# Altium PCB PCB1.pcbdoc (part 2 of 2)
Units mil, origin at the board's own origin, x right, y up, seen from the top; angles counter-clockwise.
Board outline 3879.65 x 2893.58 mil, 4 copper layers (Top Layer, Inner1, Inner2, Bottom Layer); 142 components, 140 nets, 675 pads, 157 vias.
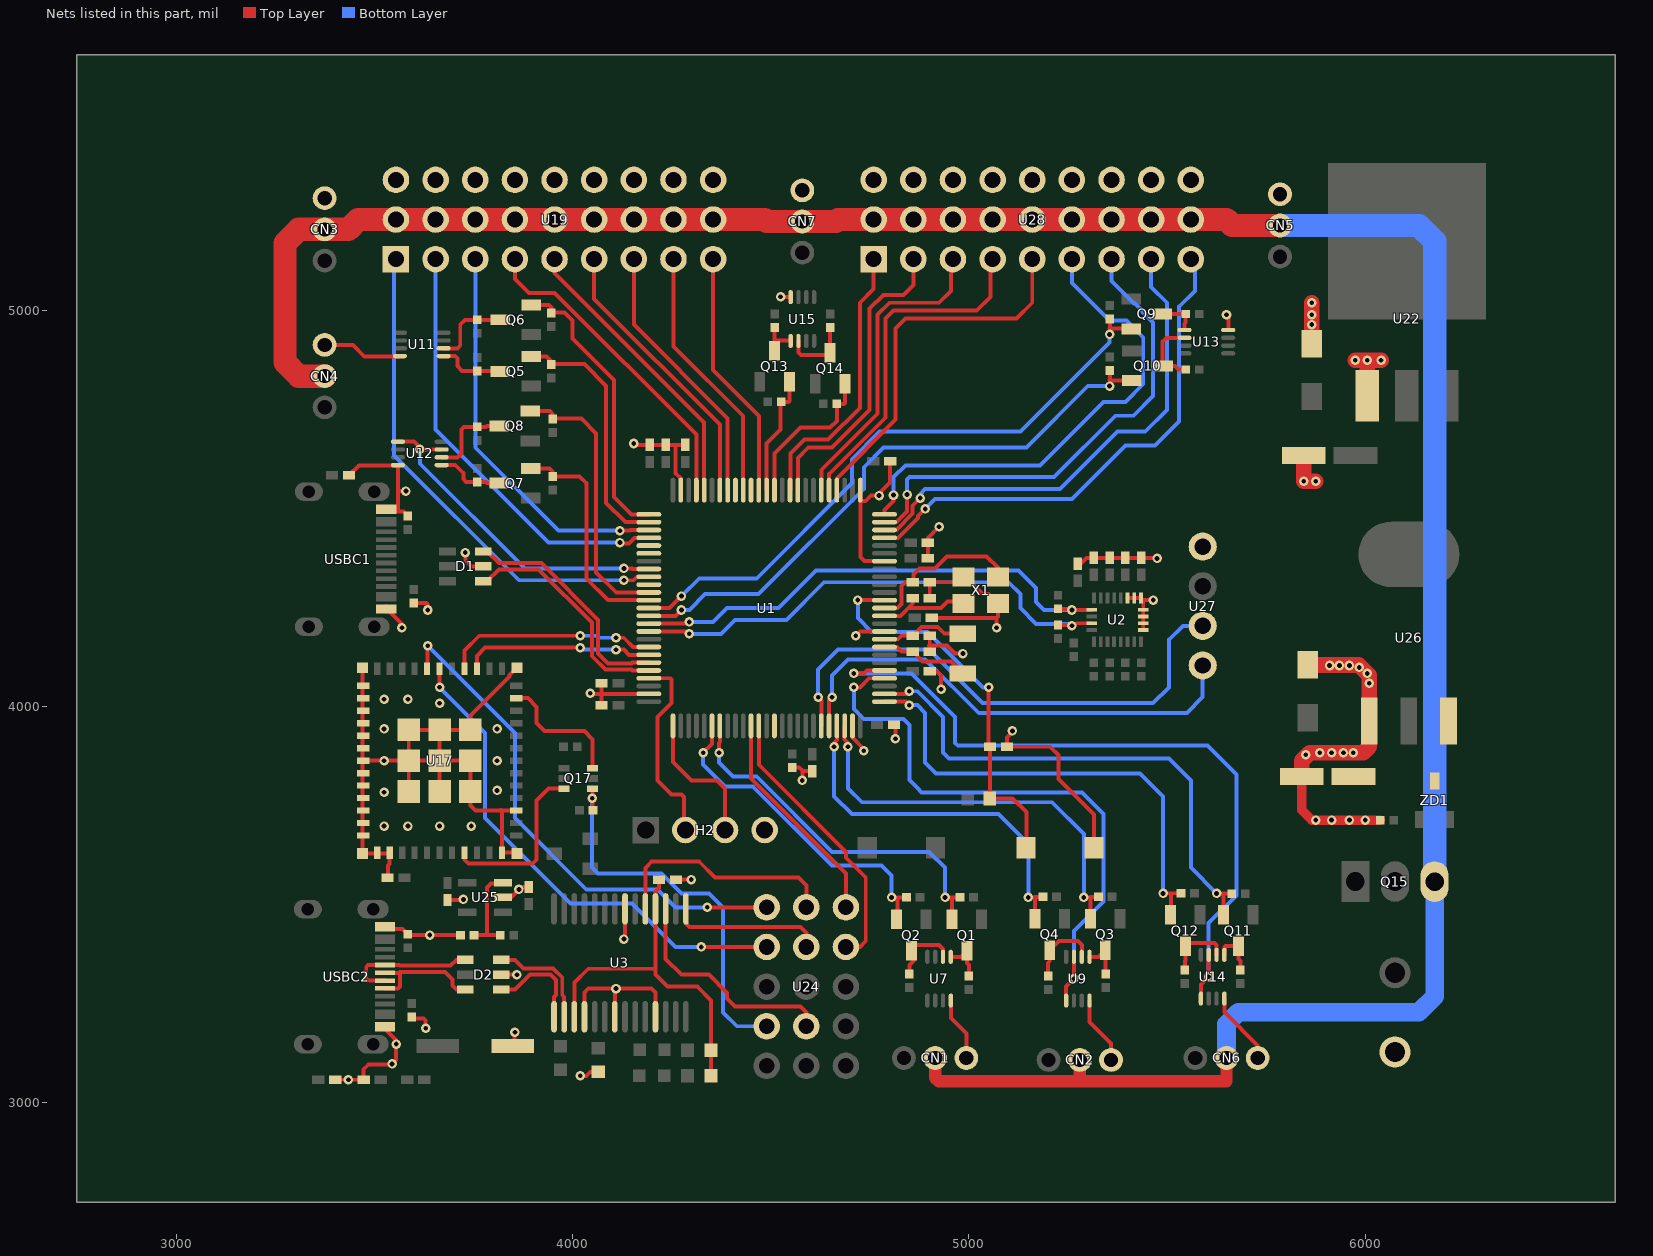
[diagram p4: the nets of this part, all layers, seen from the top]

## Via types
v1: diameter 24.02, hole 12.01, Top Layer to Bottom Layer, 157 vias

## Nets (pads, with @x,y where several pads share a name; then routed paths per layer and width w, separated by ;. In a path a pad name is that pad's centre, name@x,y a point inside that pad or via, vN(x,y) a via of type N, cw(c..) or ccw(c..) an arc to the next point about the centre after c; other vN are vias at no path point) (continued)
DUP8: U1.4 U9.1 U9.7 | length 1530.6
  Top Layer w10: v1(4709.65,4048.58) 4724.65,4048.58 4747.48,4071.41 U1.4@4786.89,4071.41 ; U9.1@5245.12,3258.36 5244.65,3258.83 5244.65,3293.58 5264.81,3313.74 U9.7@5264.81,3368.8
  Bottom Layer w10: v1(4709.65,4048.58) 4709.65,3993.58 4734.65,3968.58 4834.65,3968.58 4849.65,3953.58 4849.65,3815.1 4870.4,3794.34 ; 4872.15,3792.6 4870.4,3794.34 ; v1(5264.65,3313.58) 5264.65,3433.58 5339.65,3508.58 5339.65,3728.58 5284.65,3783.58 4879.65,3783.58 4870.4,3794.34
DUP9: U1.58 U12.1 U12.7 | length 841.8
  Top Layer w10: U12.1@3559.43,4668.11 3600.12,4668.11 3619.65,4648.58 3669.71,4648.58 U12.7@3669.87,4648.42 ; v1(4129.65,4348.58) 4149.65,4348.58 4151.22,4347.01 U1.58@4192.41,4347.01
  Bottom Layer w10: v1(3614.65,4648.58) 3614.65,4613.58 3879.65,4348.58 v1(4129.65,4348.58)
DUP10: U1.5 U14.1 U14.7 | length 1846.6
  Top Layer w10: v1(4709.65,4083.58) 4734.65,4083.58 4742.17,4091.1 U1.5@4786.89,4091.1 ; U14.1@5585.12,3263.36 5585.12,3299.05 v1(5604.65,3318.58) 5604.65,3373.64 U14.7@5604.81,3373.8
  Bottom Layer w10: v1(4709.65,4083.58) 4854.65,4083.58 4964.65,3973.58 4964.65,3908.58 4971.72,3901.51 5601.72,3901.51 5674.65,3828.58 5674.65,3523.58 5604.65,3453.58 v1(5604.65,3318.58)
EN: Q17.3 U17.8 | length 439.5
  Top Layer w10: U17.8@3727.64,3631.3 3727.64,3613.58 3737.64,3603.58 3899.65,3603.58 3909.65,3613.58 3909.65,3763.58 3939.65,3793.58 3977.84,3793.58 Q17.3@3978.43,3792.99
ESP_RX: U17.30 U24.12 | length 1269.5
  Top Layer w10: v1(3664.65,4048.58) U17.30@3664.65,4095.86 ; v1(4324.65,3393.58) U24.12@4489.65,3393.58
  Bottom Layer w10: v1(3664.65,4048.58) 3779.65,3933.58 3779.65,3718.58 3994.65,3503.58 4149.65,3503.58 4259.65,3393.58 v1(4324.65,3393.58)
ESP_TX: U17.31 U24.15 | length 1312.7
  Top Layer w10: U17.31@3633.15,4095.86 3634.65,4097.36 v1(3634.65,4153.58) ; v1(4339.65,3493.58) U24.15@4489.65,3493.58
  Bottom Layer w10: v1(3634.65,4153.58) 3854.65,3933.58 3854.65,3718.58 4034.65,3538.58 4214.65,3538.58 4259.65,3493.58 v1(4339.65,3493.58)
FTDI_DN: D2.4 USBC2.A7 USBC2.B7 | length 337.9
  Top Layer w10: USBC2.A7@3527.05,3308.74 3484.49,3308.74 3479.65,3313.58 3479.65,3343.58 3484.18,3348.11 USBC2.B7@3527.05,3348.11 3562.64,3348.11 3564.49,3346.27 3692.33,3346.27 3707.05,3360.98 D2.4@3729.41,3360.98
FTDI_DP: D2.6 USBC2.A6 USBC2.B6 | length 304.2
  Top Layer w10: USBC2.B6@3527.05,3289.05 3527.52,3288.58 3559.65,3288.58 3564.65,3293.58 3564.65,3328.58 ; USBC2.A6@3527.05,3328.42 3562.64,3328.42 3563.73,3329.5 ; 3564.65,3330.27 3678.69,3330.27 3697.32,3311.64 3697.32,3295.91 3707.05,3286.18 D2.6@3729.41,3286.18
GND: C1.1 C2.2 C3.1 C4.1 C5.2 C6.2 C7.2 C8.2 C9.2 C10.2 C11.2 C12.2 C13.2 C14.2 C15.1 C16.1 C17.1 C18.1 C19.2 C20.1 C21.1 C22.1 C23.2 C24.1 C25.2 C26.2 C27.1 C39.2 C42.1 C43.1 C44.2 C45.2 C46.2 C47.2 CN1.3 CN2.3 CN3.3 CN4.3 CN5.3 CN6.3 CN7.3 D1.2 D2.2 H2.4 P1.2 R1.1 R2.2 R3.1 R11.1 R12.2 R14.2 R45.1 R49.1 RST.1 U1.10 U1.19 U1.26 U1.49 U1.74 U1.99 U2.14 U2.15 U2.16 U2.17 U2.18 U2.19 U2.20 U3.7 U3.18 U3.21 U3.25 U7.4 U9.4 U11.4 U12.4 U13.4 U14.4 U15.4 U17.1 U17.2 U17.11 U17.14 U17.36 U17.37 U17.38 U17.39 U17.40 U17.41 U17.42 U17.43 U17.44 U17.45 U17.46 U17.47 U17.48 U17.49 U17.50 U17.51 U17.52 U17.53 U19.3 U19.6 U19.9 U19.12 U19.15 U19.18 U19.21 U19.24 U19.27 U22.1 U25.2 U26.1 U27.1 U28.3 U28.6 U28.9 U28.12 U28.15 U28.18 U28.21 U28.24 U28.27 USBC1.A1 USBC1.A12 USBC1.B1 USBC1.B12 USBC2.A1 USBC2.A12 USBC2.B1 USBC2.B12 X1.2 X1.4 | length 8404.3
  Top Layer w10: CN4.3@3374.65,4912.32 3445.91,4912.32 3474.65,4883.58 3563.96,4883.58 U11.4@3564.43,4884.05 ; C26.2@3401.11,3058.58 v1(3434.65,3058.58) C24.1@3473.19,3058.58 3473.19,3085.05 3484.65,3096.51 3542.58,3096.51 3555.08,3109.02 v1(3555.08,3148.58) 3555.08,3158.66 USBC2.A12@3527.05,3186.69 USBC2.B1@3527.05,3198.5 ; C2.2@3436.11,4583.58 3461.11,4608.58 3558.96,4608.58 U12.4@3559.43,4609.05 3559.43,4493.8 3559.65,4493.58 ; U17.50@3469.77,4097.83 U17.53@3469.77,3629.33 3536.7,3629.33 U17.2@3538.67,3631.3 3538.67,3602.6 3534.65,3598.58 3534.65,3570.04 C43.1@3533.19,3568.58 ; U17.42@3471.74,3863.58 v1(3524.65,3863.58) U17.49@3586.89,3863.58 ; USBC2.A1@3527.05,3450.47 USBC2.B12@3527.05,3438.66 3571.61,3438.66 R12.2@3584.65,3425.62 3586.69,3423.58 v1(3639.65,3423.58) R49.1@3717.61,3423.58 ; USBC1.B1@3529.8,4251.84 USBC1.A12@3529.8,4240.03 3538.2,4240.03 3569.65,4208.58 v1(3569.65,4198.58) ; USBC1.B12@3529.8,4492 3573.26,4492 R2.2@3584.65,4480.62 ; 3559.65,4543.58 v1(3579.65,4543.58) ; U17.49@3586.89,3785.82 U17.49@3586.89,3863.58 ; R11.1@3594.65,3216.54 3597.61,3213.58 3624.65,3213.58 3629.65,3208.58 v1(3629.65,3188.58) ; R1.1@3599.65,4261.54 3631.69,4261.54 3634.65,4258.58 v1(3634.65,4243.58) ; U17.49@3664.65,3785.82 U17.49@3664.65,3863.58 ; C42.1@3684.65,3512.12 3723.19,3512.12 v1(3724.65,3513.58) ; v1(3729.65,4388.58) 3729.65,4368.58 3744.65,4353.58 D1.2@3774.89,4353.58 ; 3819.65,3738.58 3820.63,3737.6 ; D2.2@3819.89,3323.58 v1(3859.65,3323.58) ; U25.2@3825.07,3518.58 3844.65,3518.58 3871.11,3545.04 C39.2@3884.65,3545.04 ; C25.2@3854.14,3138.58 3854.14,3178.07 v1(3854.65,3178.58) ; U17.14@3857.56,3737.6 3820.63,3737.6 ; U17.52@3859.53,3629.33 3857.56,3631.3 U17.11@3822.13,3631.3 3822.13,3736.1 3820.63,3737.6 ; U17.51@3859.53,4097.83 3840.99,4079.29 3840.99,4075.56 3742.41,3976.99 U17.49@3742.41,3941.34 U17.49@3664.65,3941.34 ; v1(4019.65,3068.58) 4034.65,3068.58 4044.65,3078.58 4064.31,3078.58 R14.2@4064.65,3078.92 ; U3.18@4030.08,3217.55 4030.08,3279.01 4039.65,3288.58 v1@4104.65,3288.58 ; v1(4044.65,4033.58) 4046.19,4032.04 4073.19,4032.04 ; C5.2@4073.19,4013.58 4073.19,4032.04 ; C7.2@4073.19,4058.58 4073.19,4032.04 ; U3.21@4106.85,3217.55 4106.85,3286.38 v1@4104.65,3288.58 ; v1(4129.65,3413.58) 4132.44,3416.37 U3.7@4132.44,3489.61 ; v1(4154.65,4663.58) 4158.19,4660.04 C14.2@4194.65,4660.04 C13.2@4234.65,4660.04 C4.1@4284.65,4660.04 ; U1.74@4192.41,4032.04 4073.19,4032.04 ; U3.25@4209.22,3217.55 4209.65,3217.98 4209.65,3278.58 4199.65,3288.58 v1@4104.65,3288.58 ; 4259.65,4658.58 4259.65,4588.58 4259.93,4588.3 4260.42,4588.3 4273.11,4575.62 U1.49@4273.11,4545.82 ; C27.1@4261.11,3563.58 v1(4299.65,3563.58) ; v1(4524.65,5033.58) 4549.38,5033.58 U15.4@4550.22,5032.74 ; R3.1@4554.65,3846.54 4571.69,3846.54 4579.65,3838.58 v1(4579.65,3813.58) ; 4581.11,3837.12 C3.1@4604.65,3837.12 ; U1.99@4706.19,3951.34 4706.19,3921.55 4734.65,3893.09 v1(4734.65,3888.58) ; v1(4714.65,4178.58) 4725.59,4189.52 U1.10@4786.89,4189.52 ; U1.26@4725.87,4545.82 U1.26@4725.87,4518.58 ; U1.19@4786.89,4366.69 4736.54,4366.69 4725.87,4377.36 U1.26@4725.87,4518.58 ; C12.2@4801.11,4618.58 4801.11,4565.04 4773.32,4537.25 v1(4773.32,4532.34) 4753.4,4532.34 4739.65,4518.58 U1.26@4725.87,4518.58 ; C6.2@4811.11,3953.58 4814.65,3950.04 v1(4814.65,3918.58) ; C11.2@4896.11,4378.58 4896.11,4425.04 v1(4924.65,4453.58) ; 4899.65,4153.58 4901.11,4153.58 ; C8.2@4901.11,4088.58 4919.65,4088.58 4929.65,4078.58 v1(4929.65,4043.58) ; C17.1@4901.11,4138.58 4901.11,4153.58 ; C18.1@4901.11,4178.58 4901.11,4153.58 ; C15.1@4901.11,4273.58 C16.1@4901.11,4313.58 4972.87,4313.58 X1.4@4986.34,4327.05 4991.18,4327.05 5034.65,4283.58 5048.79,4283.58 5072.25,4260.12 X1.2@5072.96,4260.12 5072.96,4226.89 5069.65,4223.58 ; C9.2@4906.11,4223.58 5069.65,4223.58 ; U7.4@4954.18,3258.36 4954.18,3214.05 4993.39,3174.84 CN1.3@4993.39,3113.58 ; v1(4984.65,4133.58) 4964.65,4133.58 4944.65,4153.58 4901.11,4153.58 ; v1(5069.65,4198.58) 5069.65,4223.58 ; v1(5109.65,3938.58) 5109.65,3935.66 5096.11,3922.12 C1.1@5096.11,3898.58 5204.65,3898.58 5225.67,3877.56 5225.67,3817.56 5315.67,3727.56 RST.1@5315.67,3643.58 ; C19.2@5274.65,4360.04 5281.11,4360.04 5296.11,4375.04 C20.1@5314.65,4375.04 C22.1@5354.65,4375.04 C21.1@5394.65,4375.04 C23.2@5434.65,4375.04 5473.19,4375.04 v1(5474.65,4373.58) ; U9.4@5304.18,3258.36 5304.18,3204.05 5358.39,3149.84 CN2.3@5358.39,3108.58 ; U2.20@5400.04,4273.7 U2.19@5416.97,4273.7 U2.18@5433.9,4273.7 5439.61,4267.99 U2.17@5439.61,4243.97 U2.16@5439.61,4227.04 U2.15@5439.61,4210.11 U2.14@5439.61,4193.19 ; 5439.65,4268.58 v1(5464.65,4268.58) ; U14.4@5644.18,3263.36 5644.18,3229.05 5728.39,3144.84 CN6.3@5728.39,3113.58 ; v1(5649.65,4988.58) 5654.65,4983.58 5654.65,4950.51 U13.4@5654,4949.87 ; U17.49@3586.89,3863.58 U17.49@3664.65,3863.58 ; U17.49@3586.89,3863.58 U17.49@3586.89,3941.34 U17.49@3664.65,3941.34 ; U17.49@3664.65,3863.58 U17.49@3742.41,3863.58 U17.49@3742.41,3785.82 3742.41,3750.82 3755.63,3737.6 3820.63,3737.6 ; U17.49@3664.65,3863.58 U17.49@3664.65,3941.34
  Top Layer w23.62: C47.2@5839.27,3823.58 5839.27,3738.96 5864.65,3713.58 v1(5914.65,3713.58) v1(5959.65,3713.58) v1(5999.65,3713.58) R45.1@6037.61,3713.58
  Top Layer w39.37: C47.2@5839.27,3823.58 5839.27,3863.21 5859.65,3883.58 v1(5884.65,3883.58) v1(5914.65,3883.58) v1(5944.65,3883.58) v1(5969.65,3883.58) 5994.65,3883.58 6009.65,3898.58 U26.1@6009.65,3963.44 v1(6009.65,4058.58) 6009.65,4078.58 5983.26,4104.97 C46.2@5854.65,4104.97 ; C44.2@5844.27,4633.58 5844.65,4633.21 v1(5844.65,4568.58) v1(5874.65,4568.58) ; C45.2@5864.65,4914.97 5864.86,4915.19 v1@5864.86,4958.58 ; v1(5864.65,4963.58) 5864.86,4963.8 v1(5864.86,4988.58) 5864.86,5018.37 v1(5864.65,5018.58) ; v1(5974.65,4873.58) v1(6004.65,4873.58) ; U22.1@6004.65,4783.63 v1(6004.65,4873.58) ; v1(6039.65,4873.58) v1(6004.65,4873.58)
  other v1: 3544.65,3098.58 4109.65,3288.58 3864.65,3538.58 3524.65,3698.58 3584.65,3698.58 3664.65,3698.58 3744.65,3698.58 5874.65,3713.58 3524.65,3783.58 3809.65,3788.58 3809.65,3863.58 5849.65,3878.58 3524.65,3943.58 3809.65,3943.58 3664.65,4008.58 3524.65,4018.58 3584.65,4018.58 6004.65,4083.58 5984.65,4098.58 5909.65,4103.58 5934.65,4103.58 5959.65,4103.58
I00: Q17.6 U17.23 | length 332.9
  Top Layer w10: U17.23@3857.56,4021.06 3887.17,4021.06 3909.65,3998.58 3909.65,3958.58 3929.65,3938.58 4029.65,3938.58 4050.86,3917.37 Q17.6@4050.86,3844.17
NRST: C1.2 C28.2 RST.2 U1.14 | length 994.1
  Top Layer w10: v1(4719.65,4268.58) 4719.96,4268.27 U1.14@4786.89,4268.27 ; v1(5049.65,4048.58) 5049.65,3902.12 C1.2@5053.19,3898.58 5053.19,3769.56 C28.2@5052.21,3768.58 5109.65,3768.58 5144.65,3733.58 5144.65,3644.6 RST.2@5143.63,3643.58
  Bottom Layer w10: v1(4719.65,4268.58) 4719.65,4223.58 4754.65,4188.58 4895.51,4188.58 5035.51,4048.58 v1(5049.65,4048.58)
OSC32_IN: C17.2 U1.8 X2.2 | length 225.4
  Top Layer w10: U1.8@4786.89,4150.15 4818.08,4150.15 4829.65,4138.58 C17.2@4858.19,4138.58 4883.19,4113.58 4954.45,4113.58 X2.2@4984.65,4083.38
OSC32_OUT: C18.2 U1.9 X2.1 | length 217.1
  Top Layer w10: U1.9@4786.89,4169.84 4820.91,4169.84 4829.65,4178.58 C18.2@4858.19,4178.58 4879.8,4200.2 4921.21,4200.2 4937.62,4183.78 X2.1@4984.65,4183.78
OSC_IN: C15.2 U1.12 X1.1 | length 241.1
  Top Layer w10: U1.12@4786.89,4228.9 4826.79,4228.9 4858.19,4260.3 C15.2@4858.19,4273.58 ; 4849.65,4248.58 4929.65,4248.58 4946.18,4265.12 X1.1@4986.34,4265.12
OSC_OUT: C16.2 U1.13 X1.3 | length 412.1
  Top Layer w10: U1.13@4786.89,4248.58 4819.65,4248.58 4829.65,4258.58 4829.65,4303.58 4839.65,4313.58 C16.2@4858.19,4313.58 4859.65,4315.04 4859.65,4333.58 4874.65,4348.58 4914.65,4348.58 4944.65,4378.58 5044.65,4378.58 5072.96,4350.27 X1.3@5072.96,4327.05
PA0: U1.22 U28.25 | length 1297.5
  Top Layer w10: U1.22@4786.89,4425.75 4821.46,4425.75 4871.87,4476.16 4871.87,4480.81 v1(4889.65,4498.58)
  Bottom Layer w10: v1(4889.65,4498.58) 4914.65,4523.58 5259.65,4523.58 5394.65,4658.58 5469.65,4658.58 5529.65,4718.58 5529.65,5008.58 5569.65,5048.58 5569.65,5118.58 U28.25@5559.65,5128.58
PA1: U1.23 U28.22 | length 1252.7
  Top Layer w10: U1.23@4786.89,4445.43 4816.81,4445.43 4857.85,4486.47 4857.85,4506.53 v1(4877.2,4525.88)
  Bottom Layer w10: v1(4877.2,4525.88) 4877.2,4536.14 4889.65,4548.58 5229.65,4548.58 5374.65,4693.58 5444.65,4693.58 5499.65,4748.58 5499.65,5018.58 5459.65,5058.58 U28.22@5459.65,5128.58
PA2: U1.24 U28.19 | length 1246.8
  Top Layer w10: U1.24@4786.89,4465.12 4816.68,4465.12 4843.84,4492.28 v1(4843.84,4534.7)
  Bottom Layer w10: v1(4843.84,4534.7) 4843.84,4572.77 4849.65,4578.58 5214.65,4578.58 5369.65,4733.58 5414.65,4733.58 5464.65,4783.58 5464.65,4968.58 5432.64,5000.59 5432.64,5003.11 5419.17,5016.57 5416.65,5016.57 5359.65,5073.58 U28.19@5359.65,5128.58
PA3: U1.25 U28.16 | length 1245
  Top Layer w10: U1.25@4786.89,4484.8 4786.89,4495.82 4809.65,4518.58 v1(4809.65,4533.58)
  Bottom Layer w10: v1(4809.65,4533.58) 4809.65,4578.58 4839.65,4608.58 5179.65,4608.58 5339.65,4768.58 5394.65,4768.58 5439.65,4813.58 5439.65,4931.07 5397.13,4973.58 5354.65,4973.58 5259.65,5068.58 U28.16@5259.65,5128.58
PA5: U1.29 U28.13 | length 950.9
  Top Layer w10: U1.29@4666.82,4545.82 4666.82,4575.75 4814.65,4723.58 4814.65,4953.58 4839.65,4978.58 5119.65,4978.58 5159.65,5018.58 U28.13@5159.65,5128.58
PA6: U1.30 U28.10 | length 876.6
  Top Layer w10: U1.30@4647.13,4545.82 4647.13,4586.06 4789.65,4728.58 4789.65,4978.58 4809.65,4998.58 5019.65,4998.58 5054.65,5033.58 5054.65,5123.58 U28.10@5059.65,5128.58
PA7: U1.31 U28.7 | length 793.6
  Top Layer w10: U1.31@4627.45,4545.82 4627.45,4596.38 4769.65,4738.58 4769.65,4988.58 4799.65,5018.58 4924.65,5018.58 4954.65,5048.58 4954.65,5123.58 U28.7@4959.65,5128.58
PB0: U1.34 U28.4 | length 767.8
  Top Layer w10: U1.34@4568.39,4545.82 4568.39,4627.32 4594.65,4653.58 4654.65,4653.58 4749.65,4748.58 4749.65,5003.58 4784.65,5038.58 4834.65,5038.58 4859.65,5063.58 U28.4@4859.65,5128.58
PB1: U1.35 U28.1 | length 705.3
  Top Layer w10: U1.35@4548.71,4545.82 4549.65,4546.76 4549.65,4638.58 4584.65,4673.58 4644.65,4673.58 4724.65,4753.58 4724.65,5018.58 4759.65,5053.58 U28.1@4759.65,5128.58
PB3: U1.89
PB10: U1.46 U19.13 | length 739.1
  Top Layer w10: U19.13@3954.65,5128.58 3954.65,5093.58 4332.17,4716.06 U1.46@4332.17,4545.82
PB11: U1.47 U19.10 | length 810.5
  Top Layer w10: U19.10@3854.65,5128.58 3854.65,5078.58 3889.65,5043.58 3954.65,5043.58 4312.48,4685.75 U1.47@4312.48,4545.82
PB14: U1.53 U19.7 | length 1000.5
  Top Layer w10: v1(4119.65,4443.58) 4144.65,4443.58 4146.5,4445.43 U1.53@4192.41,4445.43
  Bottom Layer w10: U19.7@3754.65,5128.58 3754.65,4653.58 3964.65,4443.58 v1(4119.65,4443.58)
PB15: U1.54 U19.4 | length 1092.9
  Top Layer w10: v1(4119.65,4413.58) 4122.15,4411.08 4142.15,4411.08 4156.82,4425.75 U1.54@4192.41,4425.75
  Bottom Layer w10: U19.4@3654.65,5128.58 3654.65,4698.58 3939.65,4413.58 v1(4119.65,4413.58)
PD12: U1.59 U19.1 | length 1273.9
  Top Layer w10: v1(4129.65,4318.58) 4153.87,4318.58 4162.61,4327.32 U1.59@4192.41,4327.32
  Bottom Layer w10: U19.1@3554.65,5128.58 3549.65,5123.58 3549.65,4633.58 3864.65,4318.58 v1(4129.65,4318.58)
PD13: U1.60
PE9: U1.39 U19.25 | length 630.5
  Top Layer w10: U19.25@4354.65,5128.58 4354.65,4848.58 4469.96,4733.27 U1.39@4469.96,4545.82
PE10: U1.40
PE11: U1.41 U19.22 | length 655.6
  Top Layer w10: U19.22@4254.65,5128.58 4254.65,4908.58 4430.59,4732.64 U1.41@4430.59,4545.82
PE12: U1.42
PE13: U1.43 U19.19 | length 680.8
  Top Layer w10: U19.19@4154.65,5128.58 4154.65,4963.58 4391.22,4727.01 U1.43@4391.22,4545.82
PE14: U1.44 U19.16 | length 714
  Top Layer w10: U19.16@4054.65,5128.58 4054.65,5028.58 4371.54,4711.69 U1.44@4371.54,4545.82
RTS: U3.3 U24.5 | length 580.2
  Top Layer w10: U3.3@4234.81,3489.61 4234.81,3363.42 4274.65,3323.58 4343.79,3323.58 4389.65,3277.72 4389.65,3263.58 4409.65,3243.58 4574.65,3243.58 4589.65,3228.58 U24.5@4589.65,3193.58
RTS1: Q17.4 R46.2 U24.6 | length 990.7
  Top Layer w10: Q17.4@4050.86,3792.99 4050.86,3739.41 R46.2@4051.69,3738.58
  Bottom Layer w10: v1(4049.65,3768.58) 4049.65,3593.58 4064.65,3578.58 4224.65,3578.58 4274.65,3528.58 4344.65,3528.58 4379.65,3493.58 4379.65,3228.58 4414.65,3193.58 U24.6@4489.65,3193.58
RX1: U3.5 U24.14 | length 595.5
  Top Layer w10: U3.5@4183.63,3489.61 4183.63,3592.56 4199.65,3608.58 4319.65,3608.58 4359.65,3568.58 4569.65,3568.58 4589.65,3548.58 U24.14@4589.65,3493.58
SCL: U1.95 U27.3 | length 1343.2
  Top Layer w10: v1(4619.65,4023.58) 4627.45,4015.78 U1.95@4627.45,3951.34
  Bottom Layer w10: v1(4619.65,4023.58) 4619.65,4093.58 4669.65,4143.58 4899.65,4143.58 5034.65,4008.58 5464.65,4008.58 5504.65,4048.58 5504.65,4168.58 5539.65,4203.58 U27.3@5589.65,4203.58
SCL_2: R5.1 U1.65 U2.2 | length 1271.2
  Top Layer w10: U1.65@4192.41,4209.21 4290.28,4209.21 v1(4294.65,4213.58) ; R5.1@5224.65,4246.54 5266.69,4246.54 5269.65,4243.58 5309.3,4243.58 U2.2@5309.69,4243.97
  Bottom Layer w10: v1(4294.65,4213.58) 4354.65,4213.58 4389.65,4248.58 4519.65,4248.58 4614.65,4343.58 5124.65,4343.58 5169.65,4298.58 5169.65,4263.58 5189.65,4243.58 v1(5259.65,4243.58)
SDA: U1.96 U27.4 | length 1234.4
  Top Layer w10: U1.96@4647.13,3951.34 4647.13,4016.06 v1(4654.65,4023.58)
  Bottom Layer w10: v1(4654.65,4023.58) 4654.65,4078.58 4694.65,4118.58 4889.65,4118.58 5024.65,3983.58 5549.65,3983.58 5589.65,4023.58 U27.4@5589.65,4103.58
SDA_2: R4.1 U1.66 U2.4 | length 1276.5
  Top Layer w10: U1.66@4192.41,4189.52 4288.71,4189.52 v1(4294.65,4183.58) ; R4.1@5224.65,4205.62 5266.69,4205.62 5271.19,4210.12 U2.4@5309.69,4210.12
  Bottom Layer w10: v1(4294.65,4183.58) 4374.65,4183.58 4409.65,4218.58 4539.65,4218.58 4634.65,4313.58 5099.65,4313.58 5129.65,4283.58 5129.65,4248.58 5169.65,4208.58 5254.65,4208.58 v1(5259.65,4203.58)
SWCLK: H2.3 U1.76 | length 355.2
  Top Layer w10: U1.76@4253.43,3951.34 4253.43,3859.8 4299.65,3813.58 4364.65,3813.58 4384.65,3793.58 H2.3@4384.65,3688.58
SWDIO: H2.2 U1.72 | length 496.5
  Top Layer w10: U1.72@4192.41,4071.41 4246.82,4071.41 4249.65,4068.58 4249.65,4008.58 4214.65,3973.58 4214.65,3813.58 4249.65,3778.58 4274.65,3778.58 4281.72,3771.51 4281.72,3691.51 H2.2@4284.65,3688.58
TX1: U3.1 U24.11 | length 385.8
  Top Layer w10: U3.1@4285.99,3489.61 4285.99,3452.24 4294.65,3443.58 4574.65,3443.58 4589.65,3428.58 U24.11@4589.65,3393.58
UART1_RX: U1.69 U17.27 | length 481.5
  Top Layer w10: U17.27@3759.14,4095.86 3759.14,4128.07 3779.65,4148.58 v1(4019.65,4148.58) ; v1(4109.65,4143.58) 4129.65,4143.58 4142.76,4130.47 U1.69@4192.41,4130.47
  Bottom Layer w10: v1(4019.65,4148.58) 4024.65,4143.58 v1(4109.65,4143.58)
UART1_TX: U1.68 U17.28 | length 537.6
  Top Layer w10: U17.28@3727.64,4095.86 3727.64,4141.57 3764.65,4178.58 v1(4019.65,4178.58) ; v1(4109.65,4173.58) 4129.19,4173.58 4152.62,4150.15 U1.68@4192.41,4150.15
  Bottom Layer w10: v1(4019.65,4178.58) 4059.65,4178.58 4064.65,4173.58 v1(4109.65,4173.58)
UART2_RX: U1.87 U24.10 | length 710.7
  Top Layer w10: U1.87@4469.96,3951.34 4469.96,3853.27 4689.65,3633.58 4689.65,3618.58 4739.65,3568.58 4739.65,3408.58 4724.65,3393.58 U24.10@4689.65,3393.58
UART2_TX: U1.86 U24.13 | length 557.4
  Top Layer w10: U1.86@4450.28,3951.34 4449.65,3950.71 4449.65,3818.58 4689.65,3578.58 U24.13@4689.65,3493.58
UART3_RX: U1.56
UART3_TX: U1.55
UART4_RX: Q2.2 R18.1 U1.81 | length 847.9
  Top Layer w10: v1(4329.65,3883.58) 4351.85,3905.78 U1.81@4351.85,3951.34 ; v1(4804.65,3518.58) 4819.65,3518.58 ; Q2.2@4817.25,3462.95 ccw(c4817.25,3465.35) 4819.65,3465.35 4819.65,3518.58 ; R18.1@4842.61,3518.58 4819.65,3518.58
  Bottom Layer w10: v1(4329.65,3883.58) 4329.65,3853.58 4384.65,3798.58 4454.65,3798.58 4654.65,3598.58 4779.65,3598.58 4804.65,3573.58 v1(4804.65,3518.58)
UART4_RXS: Q2.3 R20.1 U7.6 | length 170.5
  Top Layer w10: R20.1@4849.65,3325.62 4849.65,3348.58 4859.65,3358.58 4859.65,3389.21 4869.02,3398.58 4924.65,3398.58 4934.49,3388.74 U7.6@4934.49,3368.8
UART4_TX: Q1.2 R17.1 U1.82 | length 942.9
  Top Layer w10: v1(4369.65,3883.58) 4369.65,3908.58 4371.54,3910.47 U1.82@4371.54,3951.34 ; v1(4939.65,3518.58) 4959.65,3518.58 ; Q1.2@4957.25,3462.95 4957.25,3516.18 4959.65,3518.58 ; R17.1@4977.61,3518.58 4959.65,3518.58
  Bottom Layer w10: v1(4369.65,3883.58) 4369.65,3858.58 4404.65,3823.58 4464.65,3823.58 4654.65,3633.58 4899.65,3633.58 4939.65,3593.58 v1(4939.65,3518.58)
UART4_TXS: Q1.3 R19.1 U7.5 | length 117.4
  Top Layer w10: U7.5@4954.18,3368.8 4969.43,3368.8 4969.65,3368.58 4979.65,3368.58 Q1.3@4994.65,3383.58 ; Q1.3@4994.65,3389.21 Q1.3@4994.65,3383.58 ; R19.1@4999.65,3320.62 4999.65,3348.58 4994.65,3353.58 Q1.3@4994.65,3383.58
UART5_RX: Q6.2 R26.1 U1.51 | length 723
  Top Layer w10: Q6.2@3896.14,5013.11 3940.12,5013.11 3946.78,5006.45 R26.1@3946.78,4992.75 3947.61,4993.58 3979.65,4993.58 3999.65,4973.58 3999.65,4928.58 4104.65,4823.58 4104.65,4528.58 4148.43,4484.8 U1.51@4192.41,4484.8
UART5_RXS: Q6.3 R28.1 U11.6 | length 203.5
  Top Layer w10: U11.6@3674.87,4903.74 3699.49,4903.74 3699.65,4903.58 3709.65,4903.58 3716.72,4910.65 3716.72,4963.58 3728.76,4975.62 R28.1@3759.65,4975.62 3817.32,4975.62 Q6.3@3817.41,4975.71
UART5_TX: Q5.2 R25.1 U1.52 | length 647.7
  Top Layer w10: Q5.2@3896.14,4883.11 3934.65,4883.11 3946.78,4870.98 R25.1@3946.78,4862.75 3947.61,4863.58 4029.65,4863.58 4084.65,4808.58 4084.65,4513.58 4133.11,4465.12 U1.52@4192.41,4465.12
UART5_TXS: Q5.3 R27.1 U11.5 | length 170.1
  Top Layer w10: U11.5@3674.87,4884.05 3704.18,4884.05 3709.65,4878.58 3709.65,4858.58 3721.69,4846.54 R27.1@3759.65,4846.54 3816.57,4846.54 Q5.3@3817.41,4845.71
UART6_RX: Q10.2 R34.1 U1.64 | length 1530.8
  Top Layer w10: U1.64@4192.41,4228.9 4259.97,4228.9 v1(4274.65,4243.58) ; v1(5354.65,4808.58) 5355.44,4809.38 5355.44,4822.79 ; 5354.65,4823.58 5355.44,4822.79 ; R34.1@5355.44,4847.41 5355.44,4822.79 ; Q10.2@5411.07,4822.05 5356.18,4822.05 5355.44,4822.79
  Bottom Layer w10: v1(4274.65,4243.58) 4294.65,4243.58 4334.65,4283.58 4469.65,4283.58 4734.65,4548.58 4734.65,4603.58 4784.65,4653.58 5144.65,4653.58 5299.65,4808.58 v1(5354.65,4808.58)
UART6_RXS: Q10.3 R36.1 U13.6 | length 180.9
  Top Layer w10: U13.6@5543.56,4930.18 5498.62,4930.18 5488.78,4920.34 5488.78,4860.49 Q10.3@5489.81,4859.45 5519.66,4859.45 5528.78,4850.34 R36.1@5546.74,4850.34
UART6_TX: Q9.2 R33.1 U1.63 | length 1589.1
  Top Layer w10: U1.63@4192.41,4248.58 4244.65,4248.58 v1(4274.65,4278.58) ; v1(5354.65,4938.58) 5355.44,4939.38 5355.44,4953.58 ; 5354.65,4953.58 5355.44,4953.58 ; R33.1@5355.44,4977.41 5355.44,4953.58 ; Q9.2@5409.41,4952.94 5408.76,4953.58 5355.44,4953.58
  Bottom Layer w10: v1(4274.65,4278.58) 4319.65,4323.58 4464.65,4323.58 4704.65,4563.58 4704.65,4623.58 4774.65,4693.58 5129.65,4693.58 5354.65,4918.58 v1(5354.65,4938.58)
UART6_TXS: Q9.3 R35.1 U13.5 | length 100.4
  Top Layer w10: Q9.3@5488.15,4990.34 R35.1@5546.74,4990.34 5546.74,4968.3 5543.56,4965.12 U13.5@5543.56,4949.87
UART7_RX: Q14.2 R42.1 U1.37 | length 396.5
  Top Layer w10: U1.37@4509.33,4545.82 4509.65,4546.14 4509.65,4638.58 4574.65,4703.58 4649.65,4703.58 4666.69,4720.62 R42.1@4666.69,4763.58 4684.65,4763.58 4687.05,4765.98 Q14.2@4687.05,4814.21
UART7_RXS: Q14.3 R44.1 U15.6 | length 181.8
  Top Layer w10: U15.6@4569.91,4922.3 4569.91,4903.85 4569.65,4903.58 4569.65,4893.58 4576.72,4886.51 4649.65,4886.51 Q14.3@4649.65,4892.95 R44.1@4649.65,4956.54
UART7_TX: Q13.2 R41.1 U1.38 | length 307.7
  Top Layer w10: U1.38@4489.65,4545.82 4489.65,4663.58 4524.65,4698.58 4524.65,4766.54 R41.1@4526.69,4768.58 4544.65,4768.58 4547.05,4770.98 Q13.2@4547.05,4819.21
UART7_TXS: Q13.3 R43.1 U15.5 | length 99.7
  Top Layer w10: Q13.3@4509.65,4897.95 4509.65,4923.58 ; R43.1@4509.65,4956.54 4509.65,4923.58 ; U15.5@4550.22,4922.3 4548.94,4923.58 4509.65,4923.58
UART8_RX: Q4.2 R22.1 U1.97 | length 948
  Top Layer w10: v1(4659.65,3898.58) 4659.65,3908.58 4666.82,3915.75 U1.97@4666.82,3951.34 ; v1(5149.65,3518.58) 5164.65,3518.58 ; Q4.2@5166.41,3464.57 5166.41,3516.82 5164.65,3518.58 ; R22.1@5186.77,3520.2 5166.26,3520.2 5164.65,3518.58
  Bottom Layer w10: v1(4659.65,3898.58) 4659.65,3773.58 4704.65,3728.58 5074.65,3728.58 5149.65,3653.58 v1(5149.65,3518.58)
UART8_RXS: Q4.3 R24.1 U9.6 | length 191.2
  Top Layer w10: R24.1@5199.65,3320.62 5199.65,3353.58 5203.81,3357.75 Q4.3@5203.81,3385.83 5226.57,3408.58 5274.65,3408.58 5284.65,3398.58 5284.65,3368.96 U9.6@5284.49,3368.8
UART8_TX: Q3.2 R21.1 U1.98 | length 1056.3
  Top Layer w10: U1.98@4686.5,3951.34 4686.5,3916.73 4694.65,3908.58 v1(4694.65,3898.58) ; v1(5289.65,3518.58) 5304.65,3518.58 ; Q3.2@5306.41,3464.57 5306.41,3516.82 5304.65,3518.58 ; R21.1@5326.77,3520.2 5306.26,3520.2 5304.65,3518.58
  Bottom Layer w10: v1(4694.65,3898.58) 4694.65,3793.58 4729.65,3758.58 5209.65,3758.58 5289.65,3678.58 v1(5289.65,3518.58)
UART8_TXS: Q3.3 R23.1 U9.5 | length 107.2
  Top Layer w10: U9.5@5304.18,3368.8 5326.79,3368.8 Q3.3@5343.81,3385.83 5344.65,3384.99 R23.1@5344.65,3325.62
UART9_RX: Q8.2 R30.1 U1.61 | length 701.3
  Top Layer w10: Q8.2@3893.45,4745.13 3943.1,4745.13 3949.65,4738.58 R30.1@3949.65,4725.62 3950.11,4726.08 4022.15,4726.08 4059.65,4688.58 4059.65,4338.58 4110.28,4287.95 U1.61@4192.41,4287.95
UART9_RXS: Q8.3 R32.1 U12.6 | length 212.8
  Top Layer w10: U12.6@3669.87,4628.74 3670.03,4628.58 3709.65,4628.58 3719.65,4638.58 3719.65,4698.58 3726.69,4705.62 R32.1@3759.65,4705.62 3781.69,4705.62 3783.8,4707.73 Q8.3@3814.71,4707.73
UART9_TX: Q7.2 R29.1 U1.62 | length 584.4
  Top Layer w10: Q7.2@3894.02,4600.98 3942.25,4600.98 3949.65,4593.58 R29.1@3949.65,4580.62 4017.61,4580.62 4034.65,4563.58 4034.65,4323.58 4089.65,4268.58 4192.1,4268.58 U1.62@4192.41,4268.27
UART9_TXS: Q7.3 R31.1 U12.5 | length 173
  Top Layer w10: U12.5@3669.87,4609.05 3704.18,4609.05 3724.65,4588.58 3724.65,4573.58 3731.72,4566.51 R31.1@3759.65,4566.54 ; R31.1@3759.65,4566.54 3781.69,4566.54 3784.65,4563.58 Q7.3@3815.28,4563.58
UART10_RX: Q12.2 R38.1 U1.1 | length 1220
  Top Layer w10: U1.1@4786.89,4012.36 4840.87,4012.36 v1(4849.65,4003.58) ; v1(5489.65,3528.58) 5490.14,3529.08 R38.1@5534.78,3529.08 ; Q12.2@5508.5,3474.32 5509.65,3475.47 5509.65,3528.58
  Bottom Layer w10: v1(4849.65,4003.58) 4869.65,4003.58 4889.65,3983.58 4889.65,3858.58 4916.65,3831.57 5431.65,3831.57 5489.65,3773.58 v1(5489.65,3528.58)
UART10_RXS: Q12.3 R40.1 U14.6 | length 169.3
  Top Layer w10: R40.1@5544.65,3335.62 5544.65,3358.58 5545.9,3359.84 Q12.3@5545.9,3395.58 5553.9,3403.58 5619.65,3403.58 5624.49,3398.74 U14.6@5624.49,3373.8
UART10_TX: Q11.2 R37.1 U1.2 | length 1327.4
  Top Layer w10: U1.2@4786.89,4032.04 4843.11,4032.04 v1(4849.65,4038.58) ; v1(5624.65,3528.58) 5639.65,3528.58 ; Q11.2@5641.98,3474.32 5641.98,3526.25 5639.65,3528.58 ; R37.1@5663.01,3527.4 5661.83,3528.58 5639.65,3528.58
  Bottom Layer w10: v1(4849.65,4038.58) 4869.65,4038.58 4934.65,3973.58 4934.65,3883.58 4949.65,3868.58 5504.65,3868.58 5559.65,3813.58 5559.65,3593.58 v1(5624.65,3528.58)
UART10_TXS: Q11.3 R39.1 U14.5 | length 117.7
  Top Layer w10: U14.5@5644.18,3373.8 5644.18,3393.11 5646.65,3395.58 Q11.3@5679.38,3395.58 5679.65,3395.32 5679.65,3363.58 5684.65,3358.58 R39.1@5684.65,3335.62
USB_DN: D2.3 U3.16 | length 273.7
  Top Layer w10: D2.3@3819.89,3360.98 3854.76,3360.98 3876.16,3339.58 3951.27,3339.58 3974.1,3316.76 3974.1,3272.02 3978.9,3267.23 U3.16@3978.9,3217.55
USB_DP: D2.1 U3.15 | length 253.8
  Top Layer w10: D2.1@3819.89,3286.18 3854.76,3286.18 3892.16,3323.58 3944.65,3323.58 3958.1,3310.13 3958.1,3272.02 3953.31,3267.23 U3.15@3953.31,3217.55
USBDM_UP: D1.3 U1.70 | length 584.7
  Top Layer w10: D1.3@3774.89,4390.98 3784.6,4390.98 3814,4361.58 3921.27,4361.58 4064.65,4218.21 4064.65,4133.58 4089.29,4108.94 4149.07,4108.94 4150.91,4110.78 U1.70@4192.41,4110.78
USBDP_UP: D1.1 U1.71 | length 584.7
  Top Layer w10: D1.1@3774.89,4316.18 3784.6,4316.18 3814,4345.58 3914.65,4345.58 4048.65,4211.58 4048.65,4126.96 4082.66,4092.94 4149.07,4092.94 4150.91,4091.1 U1.71@4192.41,4091.1
VBUS_DET: R48.1 R49.2 U25.3 | length 231.5
  Top Layer w10: R49.2@3751.69,3423.58 3784.65,3423.58 ; R48.1@3817.61,3423.58 3784.65,3423.58 ; U25.3@3825.07,3555.98 3822.67,3553.58 3794.65,3553.58 3784.65,3543.58 3784.65,3423.58
VCC: C47.1 CN1.2 CN2.2 CN3.2 CN4.2 CN5.2 CN6.2 CN7.2 Q15.3 U19.2 U19.5 U19.8 U19.11 U19.14 U19.17 U19.20 U19.23 U19.26 U26.3 U28.2 U28.5 U28.8 U28.11 U28.14 U28.17 U28.20 U28.23 U28.26 ZD1.3 | length 6810.9
  Top Layer w31.5: CN1.2@4914.65,3113.58 4914.65,3063.58 4923.19,3055.04 5279.65,3055.04 ; CN2.2@5279.65,3108.58 5279.65,3055.04 ; CN6.2@5649.65,3113.58 5649.65,3055.04 5279.65,3055.04
  Top Layer w59.06: CN4.2@3374.65,4833.58 3309.65,4833.58 3274.65,4868.58 3274.65,5168.58 3309.65,5203.58 CN3.2@3374.65,5203.58 3434.65,5203.58 3459.65,5228.58 U19.2@3554.65,5228.58 U19.5@3654.65,5228.58 U19.8@3754.65,5228.58 U19.11@3854.65,5228.58 U19.14@3954.65,5228.58 U19.17@4054.65,5228.58 U19.20@4154.65,5228.58 U19.23@4254.65,5228.58 U19.26@4354.65,5228.58 4484.65,5228.58 4489.65,5223.58 CN7.2@4579.65,5223.58 4664.65,5223.58 4669.65,5228.58 U28.2@4759.65,5228.58 U28.5@4859.65,5228.58 U28.8@4959.65,5228.58 U28.11@5059.65,5228.58 U28.14@5159.65,5228.58 U28.17@5259.65,5228.58 U28.20@5359.65,5228.58 U28.23@5459.65,5228.58 U28.26@5559.65,5228.58 5649.65,5228.58 5664.65,5213.58 CN5.2@5784.65,5213.58
  Bottom Layer w47.24: CN6.2@5649.65,3113.58 5649.65,3198.58 5679.65,3228.58 6134.65,3228.58 6174.65,3268.59 Q15.3@6174.65,3558.39
  Bottom Layer w59.06: CN5.2@5784.65,5213.58 6134.65,5213.58 6174.65,5173.58 Q15.3@6174.64,3558.38
VCCIO: C27.2 R15.2 R16.2 U3.4 U3.17 | length 906.3
  Top Layer w10: U3.17@4004.49,3217.55 4004.49,3303.42 4039.65,3338.58 4209.65,3338.58 ; C27.2@4218.19,3563.58 4218.19,3542.12 4209.22,3533.15 U3.4@4209.22,3489.61 4209.65,3489.18 4209.65,3338.58 ; R16.2@4349.31,3068.58 R15.2@4349.31,3133.58 4349.31,3258.92 4314.65,3293.58 4239.65,3293.58 4209.65,3323.58 4209.65,3338.58
pads on no net: U1.3 U1.7 U1.15 U1.16 U1.17 U1.18 U1.28 U1.32 U1.33 U1.36 U1.45 U1.67 U1.77 U1.83 U1.85 U1.88 U1.90 U1.91 U1.92 U1.93 U2.9 U2.10 U2.11 U2.12 U3.6 U3.8 U3.9 U3.10 U3.11 U3.12 U3.13 U3.14 U3.24 U3.26 U3.27 U3.28 U17.4 U17.5 U17.6 U17.7 U17.9 U17.10 U17.12 U17.13 U17.15 U17.16 U17.17 U17.18 U17.19 U17.20 U17.21 U17.22 U17.24 U17.25 U17.26 U17.29 U17.32 U17.33 U17.34 U17.35 U24.3 U24.4 USBC1.A8 USBC1.B8 USBC2.A8 USBC2.B8 ZD1.2

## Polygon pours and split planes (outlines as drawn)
+3V3 on Inner2 (solid, remove dead copper): 3214.65,5363.58 6364.65,5363.58 6364.65,3003.58 3214.65,3003.58
GND on Top Layer (solid, remove dead copper, pour order 0): 3459.65,4118.58 3879.65,4118.58 3879.65,3608.58 3459.65,3608.58
VCC on Top Layer (solid, remove dead copper, pour order 2): 6169.65,4028.58 6194.65,4053.58 6349.65,4053.58 6374.65,4028.58 6374.65,3078.58 6319.65,3023.58 5929.65,3023.58 5904.65,3048.58 5904.65,3858.58 5924.65,3878.58 6149.65,3878.58 6169.65,3898.58
+5V on Top Layer (solid, remove dead copper, pour order 4): 3229.65,5378.58 3229.65,3038.58 3239.65,3028.58 5804.65,3028.58 5814.65,3038.58 5814.65,3423.58 5809.65,3428.58 5764.65,3428.58 5749.65,3443.58 5749.65,3508.58 5734.65,3523.58 5734.65,3543.58 5719.65,3558.58 5694.65,3558.58 5679.65,3573.58 5679.65,4693.58 5704.65,4718.58 5744.65,4718.58 5769.65,4693.58 5769.65,3908.58 5774.65,3903.58 6139.65,3903.58 6159.65,3923.58 6159.65,4038.58 6194.65,4073.58 6354.65,4073.58 6379.65,4098.58 6379.65,5383.58 6369.65,5393.58 3244.65,5393.58

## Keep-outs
Top Layer:
  region: 5809.65,3028.58 5894.65,3028.58 5894.65,3428.58 5864.65,3458.58 5864.65,3493.58 5769.65,3588.58 5769.65,4693.58 5744.65,4718.58 5704.65,4718.58 5679.65,4693.58 5679.65,3573.58 5694.65,3558.58 5719.65,3558.58 5734.65,3543.58 5734.65,3523.58 5749.65,3508.58 5749.65,3443.58 5764.65,3428.58 5809.65,3428.58 5814.65,3423.58 5814.65,3033.58
Board Outline Layer:
  region: 3229.65,4133.58 3444.65,4133.58 3444.65,3593.58 3229.65,3593.58
  lines w10: 3229.65,3108.58 3229.65,3588.58 cw(c3239.65,3588.58) 3239.65,3598.58 3444.65,3598.58 3444.65,4133.58 3239.65,4133.58 cw(c3239.65,4143.58) 3229.65,4143.58 3229.65,5308.58 cw(c3314.65,5308.58) 3314.65,5393.58 6304.65,5393.58 cw(c6304.65,5318.58) 6379.65,5318.58 6379.65,3113.58 cw(c6294.65,3113.58) 6294.65,3028.58 3309.65,3028.58 cw(c3309.65,3108.58) 3229.65,3108.58

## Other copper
Top Layer:
  drawing of 587 lines, arcs and shapes, not listed
Bottom Layer:
  region net VCC: 6198.27,3471.77 6151.03,3471.77 6150.9,3478.4 6150.52,3484.95 6149.94,3491.39 6149.18,3497.65 6148.29,3503.71 6147.29,3509.5 6145.12,3520.12 6142.96,3529.12 6141.06,3536.13 6139.22,3542.64 6210.09,3542.64 6208.24,3536.13 6206.35,3529.12 6204.18,3520.12 6202.01,3509.5 6201.01,3503.71 6200.12,3497.65 6199.36,3491.39 6198.78,3484.95 6198.41,3478.4
  region net VCC: 5626.02,3149.58 5673.27,3149.58 5673.54,3142.91 5674.27,3136.5 5675.29,3130.55 5676.46,3125.21 5678.65,3117.1 5679.65,3113.58 5619.65,3113.58 5620.64,3117.1 5622.84,3125.21 5624.01,3130.55 5625.03,3136.5 5625.75,3142.91
  region net +5V_USB_FIL: 4653.77,3122.39 4660.84,3129.46 4662.77,3127.7 4664.59,3126.35 4666.32,3125.37 4668,3124.73 4669.63,3124.37 4671.26,3124.25 4672.88,3124.33 4674.54,3124.57 4678.03,3125.35 4681.9,3126.24 4686.34,3126.91 4688.82,3127.04 4691.51,3127 4656.23,3091.72 4656.19,3094.41 4656.32,3096.89 4656.99,3101.33 4657.88,3105.2 4658.66,3108.69 4658.9,3110.35 4658.98,3111.97 4658.86,3113.6 4658.5,3115.23 4657.86,3116.91 4656.88,3118.64 4655.53,3120.46
  region net 5V_FTDI_FIL: 4594.65,3053.58 4584.65,3053.58 4584.48,3054.95 4583.99,3056.26 4583.23,3057.51 4582.23,3058.72 4579.65,3061 4576.55,3063.14 4569.92,3067.21 4566.99,3069.22 4565.75,3070.24 4564.7,3071.27 4614.59,3071.27 4613.54,3070.24 4612.3,3069.22 4609.37,3067.21 4602.75,3063.14 4599.64,3061 4597.06,3058.72 4596.06,3057.51 4595.3,3056.26 4594.82,3054.95
  region net RTS1: 4443.91,3188.58 4443.91,3198.58 4446.52,3198.7 4448.76,3199.03 4450.67,3199.57 4452.31,3200.3 4453.73,3201.2 4454.96,3202.26 4456.05,3203.47 4457.05,3204.81 4458.97,3207.83 4461.08,3211.2 4463.74,3214.81 4465.4,3216.66 4467.34,3218.53 4467.34,3168.64 4465.4,3170.51 4463.74,3172.36 4461.08,3175.96 4458.97,3179.33 4457.05,3182.35 4456.05,3183.69 4454.96,3184.9 4453.73,3185.97 4452.31,3186.87 4450.67,3187.6 4448.76,3188.13 4446.52,3188.47
  region net DTR1: 4443.91,3288.58 4443.91,3298.58 4446.52,3298.7 4448.76,3299.03 4450.67,3299.57 4452.31,3300.3 4453.73,3301.2 4454.96,3302.26 4456.05,3303.47 4457.05,3304.81 4458.97,3307.83 4461.08,3311.2 4463.74,3314.81 4465.4,3316.66 4467.34,3318.53 4467.34,3268.64 4465.4,3270.51 4463.74,3272.36 4461.08,3275.96 4458.97,3279.33 4457.05,3282.35 4456.05,3283.69 4454.96,3284.9 4453.73,3285.97 4452.31,3286.87 4450.67,3287.6 4448.76,3288.13 4446.52,3288.47
  region net ESP_RX: 3679.79,4040.51 3672.72,4033.44 3671.86,4034.17 3670.88,4034.8 3668.67,4035.74 3666.3,4036.33 3663.98,4036.59 3676.64,4049.25 3676.9,4046.93 3677.49,4044.56 3678.43,4042.35 3679.06,4041.37
  region net ESP_TX: 3649.79,4145.51 3642.72,4138.44 3641.86,4139.17 3640.88,4139.8 3638.67,4140.74 3636.3,4141.33 3633.98,4141.59 3646.64,4154.25 3646.9,4151.93 3647.49,4149.56 3648.43,4147.35 3649.06,4146.37
  region net ESP_TX: 4323.24,3488.58 4323.24,3498.58 4324.36,3498.67 4325.49,3498.92 4327.72,3499.82 4329.81,3501.08 4331.64,3502.53 4331.64,3484.63 4329.81,3486.08 4327.72,3487.35 4325.49,3488.24 4324.36,3488.49
  region net DTR1: 3991.06,3873.58 3991.06,3863.58 3989.94,3863.49 3988.81,3863.24 3986.57,3862.35 3984.48,3861.08 3982.65,3859.63 3982.65,3877.53 3984.48,3876.08 3986.57,3874.82 3988.81,3873.92 3989.94,3873.67
  region net RTS1: 4054.65,3752.17 4044.65,3752.17 4044.56,3753.29 4044.31,3754.42 4043.41,3756.66 4042.15,3758.75 4040.7,3760.58 4058.6,3760.58 4057.15,3758.75 4055.88,3756.66 4054.99,3754.42 4054.74,3753.29
  region net UART10_RX: 5484.65,3544.99 5494.65,3544.99 5494.74,3543.87 5494.99,3542.74 5495.88,3540.51 5497.15,3538.42 5498.6,3536.59 5480.7,3536.59 5482.15,3538.42 5483.41,3540.51 5484.31,3542.74 5484.56,3543.87
  region net UART10_TX: 5609.51,3536.65 5616.58,3543.72 5617.43,3542.99 5618.41,3542.37 5620.62,3541.42 5623,3540.84 5625.32,3540.57 5612.66,3527.91 5612.39,3530.23 5611.81,3532.61 5610.86,3534.82 5610.24,3535.8
  region net 5V_FTDI_FIL: 3994.88,3049.29 3990.06,3039.29 3982.94,3039.46 3979.1,3039.5 3975.84,3039.35 3986.48,3053.36 3986.87,3052.09 3987.53,3051.12 3988.41,3050.4 3989.48,3049.9 3990.71,3049.58 3992.04,3049.39
  region net +5V_USB_FIL: 3901.06,3473.58 3901.06,3463.58 3899.94,3463.49 3898.81,3463.24 3896.57,3462.35 3894.48,3461.08 3892.65,3459.63 3892.65,3477.53 3894.48,3476.08 3896.57,3474.82 3898.81,3473.92 3899.94,3473.67
  region net SDA_2: 4311.06,4188.58 4311.06,4178.58 4309.94,4178.49 4308.81,4178.24 4306.57,4177.35 4304.48,4176.08 4302.65,4174.63 4302.65,4192.53 4304.48,4191.08 4306.57,4189.82 4308.81,4188.92 4309.94,4188.67
  region net SCL_2: 4311.06,4218.58 4311.06,4208.58 4309.94,4208.49 4308.81,4208.24 4306.57,4207.35 4304.48,4206.08 4302.65,4204.63 4302.65,4222.53 4304.48,4221.08 4306.57,4219.82 4308.81,4218.92 4309.94,4218.67
  region net SCL_2: 5243.24,4238.58 5243.24,4248.58 5244.36,4248.67 5245.49,4248.92 5247.72,4249.82 5249.81,4251.08 5251.64,4252.53 5251.64,4234.63 5249.81,4236.08 5247.72,4237.35 5245.49,4238.24 5244.36,4238.49
  region net SDA_2: 5240.24,4203.58 5246.24,4213.58 5248.52,4213.71 5251.21,4214.03 5253.89,4214.51 5256.1,4215.05 5248.64,4198.78 5248.05,4199.82 5247.24,4200.75 5246.26,4201.57 5245.15,4202.26 5243.95,4202.82 5242.7,4203.24 5241.45,4203.49

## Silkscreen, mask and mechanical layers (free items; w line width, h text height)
Top Silkscreen Layer:
  text "GND" at 4704.65,5288.58 h45 r90
  text "GND" at 5664.65,5288.58 h45 r90
  text "GND" at 4459.65,5283.58 h45 r90
  text "GND" at 3499.65,5278.58 h45 r90
  text "VCC" at 4704.65,5188.58 h45 r90
  text "VCC" at 5669.65,5188.58 h45 r90
  text "VCC" at 4464.65,5183.58 h45 r90
  text "VCC" at 3499.65,5178.58 h45 r90
  text "SIG" at 5664.65,5098.58 h45 r90
  text "SIG" at 3494.65,5093.58 h45 r90
  text "SIG" at 4459.65,5093.58 h45 r90
  text "SIG" at 4704.65,5093.58 h45 r90
  text "GND" at 3449.65,4888.58 h45
  text "VCC" at 3449.65,4803.58 h45
  text "SIG" at 3449.65,4728.58 h45
  text "GND" at 5679.65,4373.58 h45
  text "+5V" at 5679.65,4273.58 h45
  text "SCL" at 5684.65,4173.58 h45
  text "SDA" at 5679.65,4068.58 h45
  text "3V3" at 4209.65,3748.58 h45 r90
  text "DIO" at 4309.65,3748.58 h45 r90
  text "CLK" at 4409.65,3748.58 h45 r90
  text "GND" at 4509.65,3748.58 h45 r90
  text "TX" at 4369.65,3468.58 h45
  text "RX" at 4369.65,3368.58 h45
  text "IN+" at 6369.65,3283.58 h59.06 r90
  text "DTR" at 4349.65,3263.58 h45
  text "RTS" at 4354.65,3168.58 h45
  text "IN-" at 6369.65,3088.58 h59.06 r90
Bottom Silkscreen Layer:
  text "DESIGNED BY /      P . NDIBA" at 4279.65,4913.58 h68.9
  text "MAX  /    24V" at 6294.65,3333.58 h78.74 r90
  text "IN+" at 6304.65,3283.58 h59.06 r270
  text "IN-" at 6304.65,3088.58 h59.06 r270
